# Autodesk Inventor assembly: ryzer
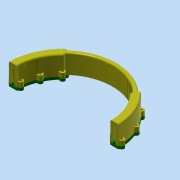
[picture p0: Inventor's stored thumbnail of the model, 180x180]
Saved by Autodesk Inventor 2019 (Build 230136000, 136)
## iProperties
Created: 2022-03
Part Number: ryzer
Material: Типовые
Document SubType Name: Assembly
Designer: mitof
Author: mitof
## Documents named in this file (3)
- C:\Users\mitof\OneDrive\Рабочий стол\3d принтер\ryzer.iam
- C:\Users\mitof\OneDrive\Рабочий стол\3d принтер\ryzen1.ipt
- C:\Users\mitof\OneDrive\Рабочий стол\3d принтер\ryzen2.ipt
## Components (2 placed, 2 different names)
1. ryzen1:1 — Жесткий:1
2. ryzen2:1 — Жесткий:1
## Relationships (1: WeldJoint 1)
- Жесткий:1 [WeldJoint]: ryzen1:1 ↔ ryzen2:1
